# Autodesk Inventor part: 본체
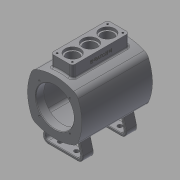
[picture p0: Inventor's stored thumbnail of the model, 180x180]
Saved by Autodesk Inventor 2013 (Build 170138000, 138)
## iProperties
Created: 2015-11
Part Number: 본체
Material: 일반
Document SubType Name: Modeling
Designer: mduedu
Density: 2.71 g/cm^3
Author: mduedu
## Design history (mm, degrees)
sketch "스케치2"
  geometry: L1 (0, 250)-(0, -250); L2 (250, 0)-(-250, 0); L3 (-50, 50)-(50, 50); L4 (50, 50)-(50, -50); L5 (50, -50)-(-50, -50); L6 (-50, -50)-(-50, 50); A1 r 90 centre (-40, 0) between (40.415, -40.415) and (40.415, 40.415); A2 r 90 centre (40, 0) between (-40.415, 40.415) and (-40.415, -40.415); A3 r 90 centre (0, -40) between (40.415, 40.415) and (-40.415, 40.415); A4 r 90 centre (0, 40) between (-40.415, -40.415) and (40.415, -40.415); 2 further points
  constraints: 12 end point, 8 point on circle, 4 centre point, 4 tangent, 3 perpendicular, 2 horizontal alignment, 2 midpoint, 2 parallel, 2 symmetric about line, 1 coincident, 1 equal radius, 1 horizontal, 1 vertical, 1 vertical alignment, 2 other
  dimensions: "d6" = 500 distance of L1.start L1.end; "d8" = 500 distance of L2.start L2.end; "d9" = 100 distance of L3.end L4.end; "d11" = 90 radius of A3
extrude "돌출1" new body sketch "스케치2" stored distance "d12" = 130; taper "d13" = 0 deg
fillet "모깎기6" dims "d30" = 15
feature "쉘1" dims "d31" = 15, "d32" = 6, "d33" = 15
sketch "스케치5"
  geometry: C1 r 35 at (0, 0); 1 further point
  constraints: 1 centre point, 1 coincident
  dimensions: "d34" = 70 diameter of C1
extrude "돌출3" cut sketch "스케치5" stored distance "d36" = 3; taper "d37" = 0 deg
fillet "모깎기14" dims "d78" = 3
sketch "스케치12"
  geometry: L1 (0, 0)-(28.284, 28.284); L2 (0, 0)-(40, 0); A1 r 40 centre (0, 0) between (28.284, 28.284) and (40, 0); 2 further points
  constraints: 4 end point, 2 coincident, 2 point on circle, 1 centre point, 1 horizontal
  dimensions: "d79" = 80 diameter of A1; "d80" = 45 deg angle of L2 L1
hole "구멍2" sketch "스케치12" at (28.284, 28.284) diameter "d82" = 3.242; stored, may be unused: countersink angle "d86" = 90 deg, drill point angle "d88" = 118 deg; dims "d83" = 9, "d84" = 10, "d85" = 2, "d87" = 11
node "작업 평면2"
sketch "스케치13"
  geometry: L1 (-52.5, -20)-(52.5, -20); L2 (52.5, -20)-(52.5, 20); L3 (52.5, 20)-(-52.5, 20); L4 (-52.5, 20)-(-52.5, -20); L5 (-52.5, -20)-(52.5, 20); L6 (52.5, -20)-(-52.5, 20); 1 further point
  constraints: 12 end point, 2 midpoint, 2 parallel, 1 horizontal, 1 perpendicular
  dimensions: "d93" = 105 distance of L2.end L3.end; "d95" = 40 distance of L1.end L2.end
extrude "돌출8" join sketch "스케치13" stored distance "d96" = 80; taper "d97" = 0 deg
fillet "모깎기15" dims "d98" = 5
fillet "모깎기16" dims "d99" = 3
sketch "스케치14"
  geometry: L1 (-52.5, 15)-(-52.5, -15) reference; L2 (52.5, -15)-(52.5, 15) reference; L3 (-52.5, 0)-(52.5, 0); 4 further points
  constraints: 2 end point, 2 midpoint, 2 point on line, 1 coincident
  dimensions: "d100" = 32 distance of point (-32, 0) point (0, 0); "d102" = 32 distance of point (32, 0) point (0, 0) (derived)
hole "구멍3" sketch "스케치14" at (-32, 0), (0, 0), (32, 0) diameter "d103" = 22; stored, may be unused: countersink angle "d107" = 90 deg, drill point angle "d109" = 118 deg; dims "d104" = 8, "d105" = 28, "d106" = 5, "d108" = 10
sketch "스케치15"
  geometry: L1 (46.5, -14)-(-46.5, -14); L2 (-46.5, -14)-(-46.5, 14); L3 (-46.5, 14)-(46.5, 14); L4 (46.5, 14)-(46.5, -14); L5 (46.5, -14)-(-46.5, 14); L6 (-46.5, -14)-(46.5, 14); L7 (47.5, 20)-(-47.5, 20) reference; L8 (-52.5, 15)-(-52.5, -15) reference; 5 further points
  constraints: 12 end point, 4 coincident, 2 midpoint, 2 parallel, 1 horizontal, 1 perpendicular
  dimensions: "d110" = 6 distance between parallel lines of L3 L7; "d111" = 6 distance between parallel lines of L2 L8
hole "구멍4" sketch "스케치15" at (-46.5, 14), (46.5, 14), (46.5, -14), (-46.5, -14) diameter "d112" = 3.242; stored, may be unused: countersink angle "d116" = 90 deg, drill point angle "d118" = 118 deg; dims "d113" = 10, "d114" = 28, "d115" = 5, "d117" = 13
sketch "스케치16"
  geometry: L1 (33.5, 0)-(61.5, 0) reference; 2 further points
  constraints: 1 vertical alignment, 1 other
  dimensions: "d128" = 11 distance from line of L1 point (47.5, -11)
feature "엠보싱2" sketch "스케치16" dims "d6" = 500, "d8" = 500, "d9" = 100, "d11" = 90, "d34" = 70, "d123" = 0.5, "d124" = 0
chamfer "모따기1" distance "d125" = 1; stored, may be unused: second distance "d126" = 2, angle "d127" = 45 deg
sketch "스케치18"
  geometry: L1 (0, 0)-(0, -80); L2 (40, -80)-(30.531, -44.663); L3 (-40, -80)-(-30.531, -44.663); L4 (-40, -80)-(40, -80); A1 r 90 centre (0, 40) between (-34.941, -42.941) and (34.941, -42.941) reference; A2 r 90 centre (0, 40) between (-30.531, -44.663) and (30.531, -44.663)
  constraints: 8 end point, 3 point on circle, 2 symmetric about line, 1 centre point, 1 coincident, 1 midpoint, 1 perpendicular, 1 vertical
  dimensions: "d132" = 80 distance of L3.start L2.start; "d134" = 75 deg angle of L4 L2; "d136" = 80 distance of L1.start L1.end
extrude "돌출9" new body sketch "스케치18" stored distance "d137" = 100; taper "d138" = 0 deg
fillet "모깎기17" dims "d139" = 10
sketch "스케치19"
  geometry: L1 (26.968, -80)-(-26.968, -80) reference; L2 (-36.627, -67.412)-(-30.531, -44.663) reference; L3 (30.531, -44.663)-(36.627, -67.412) reference; L4 (-25.775, -46.23)-(-31.797, -68.706); L5 (-26.968, -75)-(26.968, -75); L6 (31.797, -68.706)-(25.775, -46.23); L7 (0, 0)-(0, -80); A1 r 10 centre (26.968, -70) between (26.968, -80) and (36.627, -67.412) reference; A2 r 10 centre (-26.968, -70) between (-36.627, -67.412) and (-26.968, -80) reference; A3 r 90 centre (0, 40) between (-30.531, -44.663) and (30.531, -44.663) reference; A4 r 5 centre (-26.968, -70) between (-31.797, -68.706) and (-26.968, -75); A5 r 5 centre (26.968, -70) between (26.968, -75) and (31.797, -68.706); A6 r 90 centre (0, 40) between (-25.775, -46.23) and (25.775, -46.23)
  constraints: 8 end point, 7 point on circle, 3 centre point, 2 parallel, 1 coincident, 1 midpoint, 1 symmetric about line, 1 tangent, 2 other
  dimensions: "d140" = 5 distance between parallel lines of L1 L5
extrude "돌출10" cut sketch "스케치19" stored distance "d141" = 100; taper "d142" = 0 deg
sketch "스케치20"
  geometry: L1 (-30, 0)-(30, 0); L2 (30, 0)-(30, -90); L3 (30, -90)-(-30, -90); L4 (-30, -90)-(-30, 0); L5 (50, -80)-(-50, -80) reference; 2 further points
  constraints: 8 end point, 2 parallel, 1 coincident, 1 horizontal, 1 midpoint, 1 perpendicular
  dimensions: "d143" = 10 distance from line of L5 L2.end; "d144" = 60 distance of L2.end L3.end
extrude "돌출11" cut sketch "스케치20" stored distance "d145" = 100; taper "d146" = 0 deg
sketch "스케치21"
  geometry: L1 (0, 26.968)-(100, 26.968); L2 (100, 53.935)-(100, 0) reference; L3 (0, 0)-(0, 53.935) reference; L4 (0, 53.935)-(20, 53.935) reference; L5 (20, 0)-(0, 0) reference; L6 (115, 76.968)-(-15, 76.968) reference; L7 (115, -23.032)-(-15, -23.032) reference; L8 (10, 53.935)-(10, 0); L9 (50, 76.968)-(50, -23.032); C1 r 4 at (10, 41.968); C2 r 4 at (10, 11.968); C3 r 4 at (90, 41.968); C4 r 4 at (90, 11.968); 2 further points
  constraints: 6 end point, 6 midpoint, 4 centre point, 3 symmetric about line, 1 coincident, 1 horizontal, 1 point on line, 3 other
  dimensions: "d147" = 8 diameter of C1; "d148" = 15 distance from line of C1.centre L1
extrude "돌출12" cut sketch "스케치21" stored distance "d149" = 100; taper "d150" = 0 deg
feature "결합2"
  node "솔리드3"
fillet "모깎기18" dims "d151" = 1
fillet "모깎기19" dims "d152" = 2
node "솔리드1"
pattern_circular "원형 패턴1" dims angle "d90" = 360 deg
mirror "대칭3"
node "투영된 루프1"
